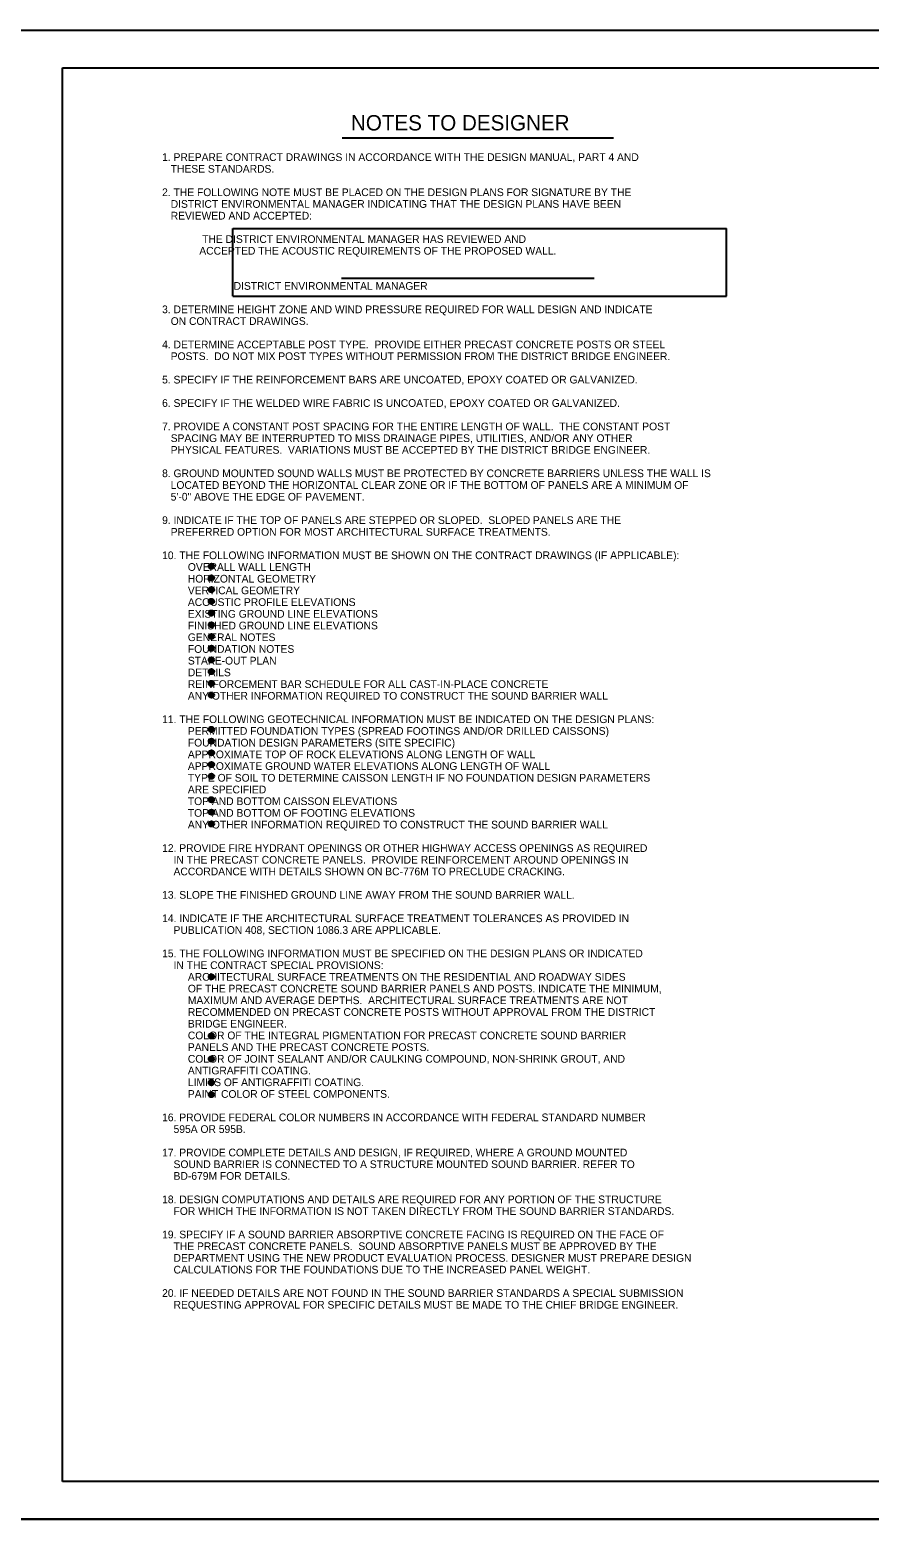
# Model space of a CAD drawing. Extents: x 3761 to 5458, y -616 to 1166.
# Drawn here: x 4629 to 4964, y 564 to 1166 of the extents above; entities that cross this region are included whole.
import ezdxf

# ---------------------------------------------------------------- set-up
doc = ezdxf.new("R2010")
doc.units = 0
for name, color, linetype in [('1', 7, 'Continuous'), ('2', 7, 'Continuous'), ('PLT-BNDY', 7, 'Continuous')]:
    doc.layers.add(name, color=color, linetype=linetype)

msp = doc.modelspace()

# ---------------------------------------------------------------- linework, layer by layer
at = {"layer": '1'}
for p, q in [((4753.92, 1122.78), (4862.14, 1122.78)), ((4710.31, 1086.6), (4907.19, 1086.6)), ((4710.31, 1059.58), (4710.31, 1086.6)), ((4907.19, 1059.58), (4907.19, 1086.6)), ((4753.59, 1066.75), (4854.38, 1066.75)), ((4710.31, 1059.58), (4907.19, 1059.58))]:
    msp.add_line(p, q, dxfattribs=at)
for centre, radius in [((4701.75, 951.81), 1.07), ((4701.75, 951.81), 0.8), ((4701.75, 951.81), 0.533), ((4701.75, 951.81), 0.267), ((4701.75, 947.14), 1.07), ((4701.75, 947.14), 0.8), ((4701.75, 947.14), 0.533), ((4701.75, 947.14), 0.267), ((4701.75, 942.47), 1.07), ((4701.75, 937.8), 1.07), ((4701.75, 942.47), 0.8), ((4701.75, 937.8), 0.8), ((4701.75, 942.47), 0.533), ((4701.75, 942.47), 0.267), ((4701.75, 933.13), 1.07), ((4701.75, 933.13), 0.8), ((4701.75, 937.8), 0.533), ((4701.75, 933.13), 0.533), ((4701.75, 937.8), 0.267), ((4701.75, 933.13), 0.267), ((4701.75, 928.45), 1.07), ((4701.75, 928.45), 0.8), ((4701.75, 928.45), 0.533), ((4701.75, 928.45), 0.267), ((4701.75, 923.78), 1.07), ((4701.75, 923.78), 0.8), ((4701.75, 923.78), 0.533), ((4701.75, 923.78), 0.267), ((4701.75, 919.11), 1.07), ((4701.75, 914.44), 1.07), ((4701.75, 919.11), 0.8), ((4701.75, 914.44), 0.8), ((4701.75, 919.11), 0.533), ((4701.75, 914.44), 0.533), ((4701.75, 919.11), 0.267), ((4701.75, 914.44), 0.267), ((4701.75, 909.77), 1.07), ((4701.75, 909.77), 0.8), ((4701.75, 909.77), 0.533), ((4701.75, 909.77), 0.267), ((4701.75, 905.09), 1.07), ((4701.75, 905.09), 0.8), ((4701.75, 905.09), 0.533), ((4701.75, 905.09), 0.267), ((4701.75, 900.42), 1.07), ((4701.75, 900.42), 0.8), ((4701.75, 900.42), 0.533), ((4701.75, 900.42), 0.267), ((4701.75, 886.72), 1.07), ((4701.75, 886.72), 0.8), ((4701.75, 886.72), 0.533), ((4701.75, 886.72), 0.267), ((4701.75, 882.04), 1.07), ((4701.75, 877.37), 1.07), ((4701.75, 882.04), 0.8), ((4701.75, 882.04), 0.533), ((4701.75, 882.04), 0.267), ((4701.75, 872.7), 1.07), ((4701.75, 877.37), 0.8), ((4701.75, 872.7), 0.8), ((4701.75, 877.37), 0.533), ((4701.75, 872.7), 0.533), ((4701.75, 877.37), 0.267), ((4701.75, 872.7), 0.267), ((4701.75, 868.03), 1.07), ((4701.75, 868.03), 0.8), ((4701.75, 868.03), 0.533), ((4701.75, 868.03), 0.267), ((4701.75, 858.68), 1.07), ((4701.75, 853.7), 1.07), ((4701.75, 858.68), 0.8), ((4701.75, 853.7), 0.8), ((4701.75, 858.68), 0.533), ((4701.75, 853.7), 0.533), ((4701.75, 858.68), 0.267), ((4701.75, 849.03), 1.07), ((4701.75, 849.03), 0.8), ((4701.75, 849.03), 0.533), ((4701.75, 853.7), 0.267), ((4701.75, 849.03), 0.267), ((4701.75, 788.01), 1.07), ((4701.75, 788.01), 0.8), ((4701.75, 788.01), 0.533), ((4701.75, 788.01), 0.267), ((4701.75, 764.45), 1.07), ((4701.75, 764.45), 0.8), ((4701.75, 764.45), 0.533), ((4701.75, 764.45), 0.267), ((4701.75, 755.27), 1.07), ((4701.75, 755.27), 0.8), ((4701.75, 755.27), 0.533), ((4701.75, 755.27), 0.267), ((4701.75, 745.79), 1.07), ((4701.75, 745.79), 0.8), ((4701.75, 745.79), 0.533), ((4701.75, 745.79), 0.267), ((4701.75, 741.04), 1.07), ((4701.75, 741.04), 0.8), ((4701.75, 741.04), 0.533), ((4701.75, 741.04), 0.267)]:
    msp.add_circle(centre, radius, dxfattribs=at)
at = {"layer": '2'}
for p, q in [((4642.34, 586.69), (4642.34, 1150.69)), ((4642.34, 1150.69), (5428.34, 1150.69)), ((5428.34, 586.69), (4642.34, 586.69))]:
    msp.add_line(p, q, dxfattribs=at)
at = {"layer": 'PLT-BNDY'}
for points in [[(4602.34, 1165.69), (5443.34, 1165.69), (5443.34, 571.69), (4602.34, 571.69)], [(4602.34, 571.69), (5443.34, 571.69), (5443.34, -22.31), (4602.34, -22.31)]]:
    msp.add_lwpolyline(points, close=True, dxfattribs=at)

# ---------------------------------------------------------------- texts
at = {"layer": '1'}
for s, height, p in [('NOTES TO DESIGNER', 6.144, (4757.42, 1125.67)), ('1. PREPARE CONTRACT DRAWINGS IN ACCORDANCE WITH THE DESIGN MANUAL, PART 4 AND', 3.072, (4682.09, 1113.5)), ('   THESE STANDARDS.', 3.072, (4682.09, 1108.83)), ('2. THE FOLLOWING NOTE MUST BE PLACED ON THE DESIGN PLANS FOR SIGNATURE BY THE', 3.072, (4682.09, 1099.49)), ('   DISTRICT ENVIRONMENTAL MANAGER INDICATING THAT THE DESIGN PLANS HAVE BEEN', 3.072, (4682.09, 1094.81)), ('   REVIEWED AND ACCEPTED:', 3.072, (4682.09, 1090.14)), ('              THE DISTRICT ENVIRONMENTAL MANAGER HAS REVIEWED AND', 3.072, (4682.09, 1080.8)), ('             ACCEPTED THE ACOUSTIC REQUIREMENTS OF THE PROPOSED WALL.', 3.072, (4682.09, 1076.13)), ('                         DISTRICT ENVIRONMENTAL MANAGER', 3.072, (4682.09, 1062.11)), ('3. DETERMINE HEIGHT ZONE AND WIND PRESSURE REQUIRED FOR WALL DESIGN AND INDICATE ', 3.072, (4682.09, 1052.77)), ('   ON CONTRACT DRAWINGS.', 3.072, (4682.09, 1048.09)), ('4. DETERMINE ACCEPTABLE POST TYPE.  PROVIDE EITHER PRECAST CONCRETE POSTS OR STEEL', 3.072, (4682.09, 1038.75)), ('   POSTS.  DO NOT MIX POST TYPES WITHOUT PERMISSION FROM THE DISTRICT BRIDGE ENGINEER.', 3.072, (4682.09, 1034.08)), ('5. SPECIFY IF THE REINFORCEMENT BARS ARE UNCOATED, EPOXY COATED OR GALVANIZED.', 3.072, (4682.09, 1024.73)), ('6. SPECIFY IF THE WELDED WIRE FABRIC IS UNCOATED, EPOXY COATED OR GALVANIZED.', 3.072, (4682.09, 1015.39)), ('7. PROVIDE A CONSTANT POST SPACING FOR THE ENTIRE LENGTH OF WALL.  THE CONSTANT POST', 3.072, (4682.09, 1006.05)), ('   SPACING MAY BE INTERRUPTED TO MISS DRAINAGE PIPES, UTILITIES, AND/OR ANY OTHER ', 3.072, (4682.09, 1001.37)), ('   PHYSICAL FEATURES.  VARIATIONS MUST BE ACCEPTED BY THE DISTRICT BRIDGE ENGINEER.', 3.072, (4682.09, 996.7)), ('8. GROUND MOUNTED SOUND WALLS MUST BE PROTECTED BY CONCRETE BARRIERS UNLESS THE WALL IS', 3.072, (4682.09, 987.36)), ('   5\'-0" ABOVE THE EDGE OF PAVEMENT.', 3.072, (4682.09, 978.01)), ('   LOCATED BEYOND THE HORIZONTAL CLEAR ZONE OR IF THE BOTTOM OF PANELS ARE A MINIMUM OF', 3.072, (4682.09, 982.69)), ('9. INDICATE IF THE TOP OF PANELS ARE STEPPED OR SLOPED.  SLOPED PANELS ARE THE', 3.072, (4682.09, 968.67)), ('   PREFERRED OPTION FOR MOST ARCHITECTURAL SURFACE TREATMENTS.', 3.072, (4682.09, 964)), ('10. THE FOLLOWING INFORMATION MUST BE SHOWN ON THE CONTRACT DRAWINGS (IF APPLICABLE):', 3.072, (4682.09, 954.65)), ('         OVERALL WALL LENGTH', 3.072, (4682.09, 949.98)), ('         HORIZONTAL GEOMETRY', 3.072, (4682.09, 945.31)), ('         ACOUSTIC PROFILE ELEVATIONS', 3.072, (4682.09, 935.97)), ('         VERTICAL GEOMETRY', 3.072, (4682.09, 940.64)), ('         EXISTING GROUND LINE ELEVATIONS', 3.072, (4682.09, 931.29)), ('         FINISHED GROUND LINE ELEVATIONS', 3.072, (4682.09, 926.62)), ('         GENERAL NOTES', 3.072, (4682.09, 921.95)), ('         FOUNDATION NOTES', 3.072, (4682.09, 917.28)), ('         STAKE-OUT PLAN', 3.072, (4682.09, 912.61)), ('         DETAILS', 3.072, (4682.09, 907.93)), ('         REINFORCEMENT BAR SCHEDULE FOR ALL CAST-IN-PLACE CONCRETE', 3.072, (4682.09, 903.26)), ('         ANY OTHER INFORMATION REQUIRED TO CONSTRUCT THE SOUND BARRIER WALL', 3.072, (4682.09, 898.59)), ('11. THE FOLLOWING GEOTECHNICAL INFORMATION MUST BE INDICATED ON THE DESIGN PLANS:', 3.072, (4682.09, 889.25)), ('         PERMITTED FOUNDATION TYPES (SPREAD FOOTINGS AND/OR DRILLED CAISSONS)', 3.072, (4682.09, 884.57)), ('         APPROXIMATE TOP OF ROCK ELEVATIONS ALONG LENGTH OF WALL', 3.072, (4682.09, 875.23)), ('         FOUNDATION DESIGN PARAMETERS (SITE SPECIFIC)', 3.072, (4682.09, 879.9)), ('         APPROXIMATE GROUND WATER ELEVATIONS ALONG LENGTH OF WALL', 3.072, (4682.09, 870.56)), ('         TYPE OF SOIL TO DETERMINE CAISSON LENGTH IF NO FOUNDATION DESIGN PARAMETERS', 3.072, (4682.09, 865.89)), ('         ARE SPECIFIED', 3.072, (4682.09, 861.21)), ('         TOP AND BOTTOM CAISSON ELEVATIONS', 3.072, (4682.09, 856.54)), ('         TOP AND BOTTOM OF FOOTING ELEVATIONS', 3.072, (4682.09, 851.87)), ('         ANY OTHER INFORMATION REQUIRED TO CONSTRUCT THE SOUND BARRIER WALL', 3.072, (4682.09, 847.2)), ('12. PROVIDE FIRE HYDRANT OPENINGS OR OTHER HIGHWAY ACCESS OPENINGS AS REQUIRED ', 3.072, (4682.09, 837.85)), ('    IN THE PRECAST CONCRETE PANELS.  PROVIDE REINFORCEMENT AROUND OPENINGS IN', 3.072, (4682.09, 833.18)), ('    ACCORDANCE WITH DETAILS SHOWN ON BC-776M TO PRECLUDE CRACKING.', 3.072, (4682.09, 828.51)), ('13. SLOPE THE FINISHED GROUND LINE AWAY FROM THE SOUND BARRIER WALL.', 3.072, (4682.09, 819.17)), ('14. INDICATE IF THE ARCHITECTURAL SURFACE TREATMENT TOLERANCES AS PROVIDED IN', 3.072, (4682.09, 809.82)), ('    PUBLICATION 408, SECTION 1086.3 ARE APPLICABLE.', 3.072, (4682.09, 805.15)), ('15. THE FOLLOWING INFORMATION MUST BE SPECIFIED ON THE DESIGN PLANS OR INDICATED', 3.072, (4682.09, 795.81)), ('    IN THE CONTRACT SPECIAL PROVISIONS:', 3.072, (4682.09, 791.13)), ('         ARCHITECTURAL SURFACE TREATMENTS ON THE RESIDENTIAL AND ROADWAY SIDES', 3.072, (4682.09, 786.46)), ('         OF THE PRECAST CONCRETE SOUND BARRIER PANELS AND POSTS. INDICATE THE MINIMUM,  ', 3.072, (4682.09, 781.79)), ('         MAXIMUM AND AVERAGE DEPTHS.  ARCHITECTURAL SURFACE TREATMENTS ARE NOT ', 3.072, (4682.09, 777.12)), ('         RECOMMENDED ON PRECAST CONCRETE POSTS WITHOUT APPROVAL FROM THE DISTRICT', 3.072, (4682.09, 772.45)), ('         BRIDGE ENGINEER.', 3.072, (4682.09, 767.77)), ('         COLOR OF THE INTEGRAL PIGMENTATION FOR PRECAST CONCRETE SOUND BARRIER', 3.072, (4682.09, 763.1)), ('         PANELS AND THE PRECAST CONCRETE POSTS.', 3.072, (4682.09, 758.43)), ('         ANTIGRAFFITI COATING.', 3.072, (4682.09, 749.09)), ('         COLOR OF JOINT SEALANT AND/OR CAULKING COMPOUND, NON-SHRINK GROUT, AND', 3.072, (4682.09, 753.76)), ('         LIMITS OF ANTIGRAFFITI COATING.', 3.072, (4682.09, 744.41)), ('         PAINT COLOR OF STEEL COMPONENTS.', 3.072, (4682.09, 739.74)), ('16. PROVIDE FEDERAL COLOR NUMBERS IN ACCORDANCE WITH FEDERAL STANDARD NUMBER', 3.072, (4682.09, 730.4)), ('    595A OR 595B.', 3.072, (4682.09, 725.73)), ('17. PROVIDE COMPLETE DETAILS AND DESIGN, IF REQUIRED, WHERE A GROUND MOUNTED ', 3.072, (4682.09, 716.38)), ('    SOUND BARRIER IS CONNECTED TO A STRUCTURE MOUNTED SOUND BARRIER. REFER TO', 3.072, (4682.09, 711.71)), ('    BD-679M FOR DETAILS.', 3.072, (4682.09, 707.04)), ('18. DESIGN COMPUTATIONS AND DETAILS ARE REQUIRED FOR ANY PORTION OF THE STRUCTURE', 3.072, (4682.09, 697.69)), ('    FOR WHICH THE INFORMATION IS NOT TAKEN DIRECTLY FROM THE SOUND BARRIER STANDARDS.', 3.072, (4682.09, 693.02)), ('19. SPECIFY IF A SOUND BARRIER ABSORPTIVE CONCRETE FACING IS REQUIRED ON THE FACE OF', 3.072, (4682.09, 683.68)), ('    THE PRECAST CONCRETE PANELS.  SOUND ABSORPTIVE PANELS MUST BE APPROVED BY THE', 3.072, (4682.09, 679.01)), ('    DEPARTMENT USING THE NEW PRODUCT EVALUATION PROCESS. DESIGNER MUST PREPARE DESIGN', 3.072, (4682.09, 674.33)), ('    CALCULATIONS FOR THE FOUNDATIONS DUE TO THE INCREASED PANEL WEIGHT.', 3.072, (4682.09, 669.66)), ('20. IF NEEDED DETAILS ARE NOT FOUND IN THE SOUND BARRIER STANDARDS A SPECIAL SUBMISSION', 3.072, (4682.09, 660.32)), ('    REQUESTING APPROVAL FOR SPECIFIC DETAILS MUST BE MADE TO THE CHIEF BRIDGE ENGINEER.', 3.072, (4682.09, 655.65))]:
    msp.add_text(s, height=height, dxfattribs=at).set_placement(p)

doc.saveas('drawing.dxf')
